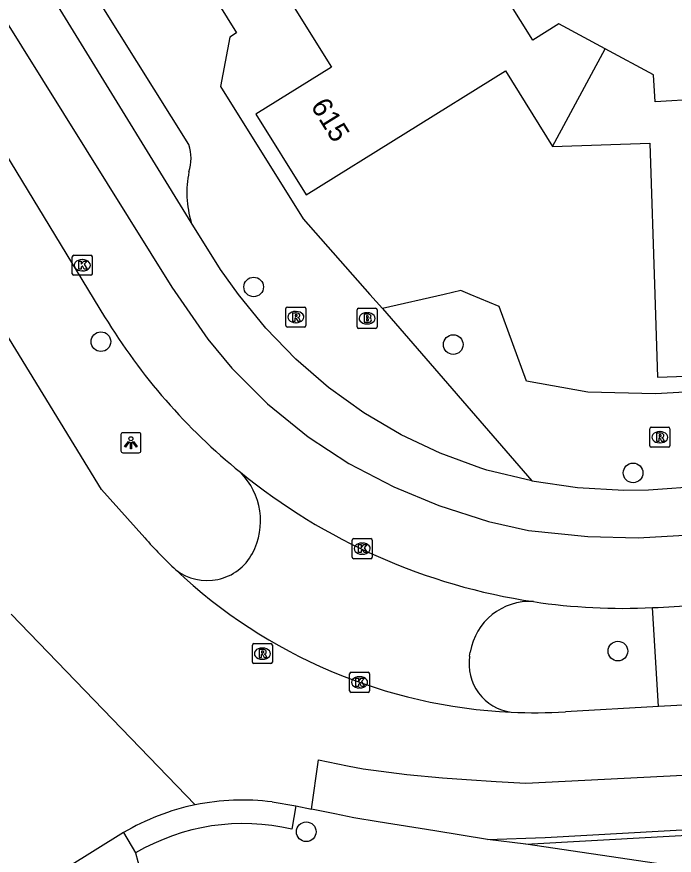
# Model space of a CAD drawing. Extents: x 158461 to 159795, y 387220 to 388672.
# Drawn here: x 158950.89 to 158983.68, y 387722.02 to 387763.85 of the extents above; entities that cross this region are included whole.
import ezdxf

# ---------------------------------------------------------------- set-up
doc = ezdxf.new("R2010")
doc.units = 0
for name, color, linetype in [('IMGEO_Boom', 7, 'Continuous'), ('IMGEO_Brandkraan', 7, 'Continuous'), ('IMGEO_Kolk', 7, 'Continuous'), ('IMGEO_Lichtpunt', 7, 'Continuous'), ('IMGEO_Pand', 7, 'Continuous'), ('IMGEO_Pand_nummerreeks', 7, 'Continuous'), ('IMGEO_Rijbaan_lokaal_gesloten', 7, 'Continuous'), ('IMGEO_Rijbaan_lokaal_open', 7, 'Continuous'), ('IMGEO_Rioolput', 7, 'Continuous'), ('IMGEO_Voetpad_open', 7, 'Continuous')]:
    doc.layers.add(name, color=color, linetype=linetype)

msp = doc.modelspace()

# ---------------------------------------------------------------- linework, layer by layer
at = {"layer": 'IMGEO_Boom'}
for centre in [(158962.704, 387750.372), (158955.083, 387747.643), (158972.658, 387747.498), (158981.631, 387741.095), (158980.875, 387732.205), (158965.326, 387723.193)]:
    msp.add_circle(centre, 0.489, dxfattribs=at)
at = {"layer": 'IMGEO_Brandkraan'}
for p, q in [((158967.862, 387748.381), (158967.862, 387749.233)), ((158967.937, 387749.307), (158968.789, 387749.307)), ((158968.863, 387749.233), (158968.863, 387748.381)), ((158968.35, 387749.087), (158968.375, 387749.087)), ((158968.789, 387748.307), (158967.937, 387748.307)), ((158968.373, 387748.527), (158968.348, 387748.527))]:
    msp.add_line(p, q, dxfattribs=at)
for points in [[(158967.862, 387748.381), (158967.862, 387749.233)], [(158967.937, 387749.307), (158968.789, 387749.307)], [(158968.863, 387749.233), (158968.863, 387748.381)], [(158968.21, 387749.007), (158968.21, 387748.607), (158968.423, 387748.607)], [(158968.441, 387749.007), (158968.21, 387749.007)], [(158968.389, 387748.926), (158968.335, 387748.926), (158968.335, 387748.85)], [(158968.335, 387748.85), (158968.388, 387748.85)], [(158968.397, 387748.774), (158968.335, 387748.774), (158968.335, 387748.693)], [(158968.335, 387748.693), (158968.397, 387748.693)], [(158968.789, 387748.307), (158967.937, 387748.307)]]:
    msp.add_lwpolyline(points, dxfattribs=at)
for centre, radius, start, end in [((158967.939, 387749.231), 0.0765, 91.552, 178.448), ((158967.939, 387749.231), 0.0765, 91.552, 178.448), ((158968.787, 387749.231), 0.0765, 1.552, 88.448), ((158968.787, 387749.231), 0.0765, 1.552, 88.448), ((158968.39, 387748.888), 0.0379, 267.8285, 90.9355), ((158968.398, 387748.733), 0.0404, 269.8759, 90.5077), ((158968.445, 387748.862), 0.145, 59.4692, 91.5367), ((158968.47, 387748.909), 0.0922, 285.5137, 58.1501), ((158968.475, 387748.717), 0.105, 301.3115, 78.989), ((158967.939, 387748.383), 0.0765, 181.552, 268.448), ((158967.939, 387748.383), 0.0765, 181.552, 268.448), ((158968.429, 387748.858), 0.251, 268.6676, 293.5347), ((158968.787, 387748.383), 0.0765, 271.552, 358.448), ((158968.787, 387748.383), 0.0765, 271.552, 358.448)]:
    msp.add_arc(centre, radius, start, end, dxfattribs=at)
for centre, major_axis, ratio, start_param, end_param in [((158968.349, 387748.807), (-0.387, 0.002), 0.722429, 4.712389, 7.853982), ((158968.374, 387748.807), (-0.39, 0.002), 0.717154, 1.570796, 4.712389)]:
    msp.add_ellipse(centre, major_axis=major_axis, ratio=ratio, start_param=start_param, end_param=end_param, dxfattribs=at)
at = {"layer": 'IMGEO_Kolk'}
for p, q in [((158953.654, 387751.028), (158953.654, 387751.88)), ((158953.729, 387751.954), (158954.581, 387751.954)), ((158954.142, 387751.734), (158954.167, 387751.734)), ((158954.655, 387751.88), (158954.655, 387751.028)), ((158954.581, 387750.954), (158953.729, 387750.954)), ((158954.165, 387751.174), (158954.14, 387751.174)), ((158967.693, 387737.817), (158968.545, 387737.817)), ((158967.618, 387736.891), (158967.618, 387737.743)), ((158968.106, 387737.597), (158968.131, 387737.597)), ((158968.619, 387737.743), (158968.619, 387736.891)), ((158968.129, 387737.037), (158968.104, 387737.037)), ((158968.545, 387736.817), (158967.693, 387736.817)), ((158967.562, 387731.148), (158968.414, 387731.148)), ((158967.487, 387730.222), (158967.487, 387731.074)), ((158967.975, 387730.928), (158968, 387730.928)), ((158968.488, 387731.074), (158968.488, 387730.222)), ((158967.998, 387730.368), (158967.973, 387730.368)), ((158968.414, 387730.148), (158967.562, 387730.148))]:
    msp.add_line(p, q, dxfattribs=at)
for points in [[(158953.654, 387751.028), (158953.654, 387751.88)], [(158953.729, 387751.954), (158954.581, 387751.954)], [(158953.975, 387751.654), (158954.098, 387751.654), (158954.098, 387751.503), (158954.228, 387751.654), (158954.392, 387751.654), (158954.246, 387751.503), (158954.399, 387751.254), (158954.247, 387751.254), (158954.162, 387751.418), (158954.098, 387751.351), (158954.098, 387751.254), (158953.975, 387751.254), (158953.975, 387751.654)], [(158954.655, 387751.88), (158954.655, 387751.028)], [(158954.581, 387750.954), (158953.729, 387750.954)], [(158967.693, 387737.817), (158968.545, 387737.817)], [(158967.618, 387736.891), (158967.618, 387737.743)], [(158967.939, 387737.517), (158968.062, 387737.517), (158968.062, 387737.366), (158968.192, 387737.517), (158968.356, 387737.517), (158968.21, 387737.366), (158968.363, 387737.117), (158968.211, 387737.117), (158968.126, 387737.281), (158968.062, 387737.214), (158968.062, 387737.117), (158967.939, 387737.117), (158967.939, 387737.517)], [(158968.619, 387737.743), (158968.619, 387736.891)], [(158968.545, 387736.817), (158967.693, 387736.817)], [(158967.562, 387731.148), (158968.414, 387731.148)], [(158967.487, 387730.222), (158967.487, 387731.074)], [(158967.808, 387730.848), (158967.931, 387730.848), (158967.931, 387730.697), (158968.061, 387730.848), (158968.225, 387730.848), (158968.079, 387730.697), (158968.232, 387730.448), (158968.08, 387730.448), (158967.995, 387730.612), (158967.931, 387730.545), (158967.931, 387730.448), (158967.808, 387730.448), (158967.808, 387730.848)], [(158968.488, 387731.074), (158968.488, 387730.222)], [(158968.414, 387730.148), (158967.562, 387730.148)]]:
    msp.add_lwpolyline(points, dxfattribs=at)
for centre, start, end in [((158953.731, 387751.878), 91.552, 178.448), ((158953.731, 387751.878), 91.552, 178.448), ((158954.579, 387751.878), 1.552, 88.448), ((158954.579, 387751.878), 1.552, 88.448), ((158953.731, 387751.03), 181.552, 268.448), ((158953.731, 387751.03), 181.552, 268.448), ((158954.579, 387751.03), 271.552, 358.448), ((158954.579, 387751.03), 271.552, 358.448), ((158967.695, 387737.741), 91.552, 178.448), ((158967.695, 387737.741), 91.552, 178.448), ((158968.543, 387737.741), 1.552, 88.448), ((158968.543, 387737.741), 1.552, 88.448), ((158967.695, 387736.893), 181.552, 268.448), ((158967.695, 387736.893), 181.552, 268.448), ((158968.543, 387736.893), 271.552, 358.448), ((158968.543, 387736.893), 271.552, 358.448), ((158967.564, 387731.072), 91.552, 178.448), ((158967.564, 387731.072), 91.552, 178.448), ((158968.412, 387731.072), 1.552, 88.448), ((158968.412, 387731.072), 1.552, 88.448), ((158967.564, 387730.224), 181.552, 268.448), ((158967.564, 387730.224), 181.552, 268.448), ((158968.412, 387730.224), 271.552, 358.448), ((158968.412, 387730.224), 271.552, 358.448)]:
    msp.add_arc(centre, 0.0765, start, end, dxfattribs=at)
for centre, major_axis, ratio, start_param, end_param in [((158954.141, 387751.454), (-0.387, 0.002), 0.722429, 4.712389, 7.853982), ((158954.166, 387751.454), (-0.39, 0.002), 0.717154, 1.570796, 4.712389), ((158968.105, 387737.317), (-0.387, 0.002), 0.722429, 4.712389, 7.853982), ((158968.13, 387737.317), (-0.39, 0.002), 0.717154, 1.570796, 4.712389), ((158967.974, 387730.648), (-0.387, 0.002), 0.722429, 4.712389, 7.853982), ((158967.999, 387730.648), (-0.39, 0.002), 0.717154, 1.570796, 4.712389)]:
    msp.add_ellipse(centre, major_axis=major_axis, ratio=ratio, start_param=start_param, end_param=end_param, dxfattribs=at)
at = {"layer": 'IMGEO_Lichtpunt'}
for p, q in [((158956.081, 387743.004), (158956.081, 387742.197)), ((158956.081, 387743.004), (158956.081, 387742.197)), ((158956.983, 387743.099), (158956.175, 387743.099)), ((158956.983, 387743.099), (158956.175, 387743.099)), ((158957.077, 387742.197), (158957.077, 387743.004)), ((158957.077, 387742.197), (158957.077, 387743.004)), ((158956.175, 387742.103), (158956.983, 387742.103)), ((158956.175, 387742.103), (158956.983, 387742.103))]:
    msp.add_line(p, q, dxfattribs=at)
for points in [[(158956.455, 387742.668), (158956.494, 387742.64), (158956.306, 387742.378), (158956.268, 387742.405), (158956.455, 387742.668)], [(158956.557, 387742.62), (158956.604, 387742.62), (158956.604, 387742.298), (158956.557, 387742.298), (158956.557, 387742.62)], [(158956.667, 387742.64), (158956.705, 387742.667), (158956.892, 387742.405), (158956.853, 387742.377), (158956.667, 387742.64)]]:
    msp.add_lwpolyline(points, dxfattribs=at)
msp.add_circle((158956.58, 387742.802), 0.0994, dxfattribs=at)
for centre, start, end in [((158956.175, 387743.004), 90, 180), ((158956.175, 387743.004), 90, 180), ((158956.983, 387743.004), 0, 90), ((158956.983, 387743.004), 0, 90), ((158956.175, 387742.197), 180, 270), ((158956.175, 387742.197), 180, 270), ((158956.983, 387742.197), 270, 0), ((158956.983, 387742.197), 270, 360)]:
    msp.add_arc(centre, 0.0946, start, end, dxfattribs=at)
at = {"layer": 'IMGEO_Pand'}
for points in [[(158980.245, 387762.254), (158977.935, 387763.495), (158976.624, 387762.679), (158974.165, 387766.629)], [(158964.468, 387764.726), (158966.581, 387761.331), (158962.812, 387758.985), (158965.317, 387754.961), (158975.259, 387761.149), (158977.604, 387757.38)], [(158977.604, 387757.38), (158980.245, 387762.254)], [(158987.15, 387759.865), (158982.73, 387759.611), (158982.652, 387760.96), (158980.245, 387762.254)], [(158977.604, 387757.38), (158982.462, 387757.541), (158982.712, 387750), (158982.849, 387745.874), (158987.604, 387746.031), (158987.473, 387750), (158987.453, 387750.601), (158991.981, 387750.857)]]:
    msp.add_lwpolyline(points, dxfattribs=at)
at = {"layer": 'IMGEO_Rijbaan_lokaal_gesloten'}
for points in [[(158887.922, 387863.502), (158910.852, 387826.792), (158942.469, 387776.24), (158958.617, 387750.353), (158960.418, 387747.762), (158961.612, 387746.321), (158963.393, 387744.535), (158965.421, 387742.895), (158967.458, 387741.572), (158969.689, 387740.407), (158971.94, 387739.465), (158974.416, 387738.664), (158976.417, 387738.226), (158979.369, 387737.931), (158981.889, 387737.858), (159007.45, 387739.32), (159019.867, 387740.171), (159032.856, 387742.163)], [(158959.591, 387753.588), (158948.358, 387771.822), (158935.188, 387792.904), (158922.531, 387813.295), (158913.231, 387828.204), (158908.724, 387835.428), (158907.553, 387837.293)], [(158950.329, 387757.013), (158955.27, 387748.888)], [(158957.267, 387737.857), (158955.113, 387740.269), (158950.163, 387748.361), (158949.133, 387750), (158946.243, 387754.475)], [(158976.58, 387740.699), (158974.334, 387741.233), (158974.035, 387741.326), (158972.009, 387742.075), (158970.058, 387743.002), (158968.197, 387744.099), (158966.443, 387745.358), (158964.807, 387746.769), (158963.304, 387748.321), (158961.946, 387750), (158961.046, 387751.246), (158959.591, 387753.588)], [(158976.58, 387740.699), (158978.865, 387740.368), (158981.171, 387740.242), (158982.397, 387740.259), (158985.18, 387740.45)], [(158982.6, 387734.374), (158982.875, 387734.389), (158984.743, 387734.496)], [(158950.607, 387734.056), (158959.793, 387724.538)], [(158982.896, 387729.442), (158978.256, 387729.175)], [(158985.039, 387729.565), (158982.896, 387729.442)], [(158965.591, 387724.322), (158965.932, 387726.779), (158967.392, 387726.477), (158968.163, 387726.336), (158970.34, 387726.046), (158972.125, 387725.889), (158973.313, 387725.803), (158974.8, 387725.707), (158976.288, 387725.617), (158996.546, 387726.65), (159030.787, 387728.616), (159033.217, 387728.616), (159034.104, 387728.548), (159034.99, 387728.468), (159035.499, 387728.412), (159036.753, 387728.237), (159037.631, 387728.097), (159038.26, 387727.989), (159043.465, 387727.098), (159045.801, 387726.729), (159046.831, 387726.625), (159048.016, 387726.551)], [(158974.362, 387722.8), (158977.244, 387722.906), (159022.96, 387725.469), (159024.209, 387725.614)], [(159022.447, 387725.145), (159009.709, 387721.727), (158989.772, 387720.574), (158976.287, 387722.576)], [(158976.287, 387722.576), (159022.447, 387725.145)], [(158963.626, 387724.68), (158964.813, 387724.483)], [(158964.813, 387724.483), (158965.591, 387724.322)], [(158974.362, 387722.8), (158971.743, 387723.241), (158968.918, 387723.697), (158967.694, 387723.895), (158966.752, 387724.082), (158965.591, 387724.322)], [(158956.215, 387723.154), (158935.881, 387710.493)]]:
    msp.add_lwpolyline(points, dxfattribs=at)
for centre, radius, start, end in [((158981.128, 387764.611), 30.263, 211.3024, 230.8935), ((158981.144, 387764.621), 30.281, 230.8811, 261.4837), ((158976.338, 387754.858), 25.549, 221.7155, 226.7238), ((158976.758, 387755.265), 26.133, 226.6651, 267.3411), ((158981.152, 387764.653), 30.314, 261.4789, 272.7385), ((158976.758, 387755.01), 25.878, 267.3157, 273.3186), ((158962.126, 387713.189), 11.586, 101.6171, 120.6767), ((158962.134, 387713.137), 11.639, 82.6373, 101.606)]:
    msp.add_arc(centre, radius, start, end, dxfattribs=at)
at = {"layer": 'IMGEO_Rijbaan_lokaal_open'}
for points in [[(158973.477, 387731.947), (158973.511, 387732.16)], [(158976.287, 387722.576), (158974.362, 387722.8)]]:
    msp.add_lwpolyline(points, dxfattribs=at)
for centre, radius, start, end in [((158959.613, 387738.697), 3.434, 331.7888, 45.0488), ((158960.385, 387738.285), 2.559, 232.4274, 331.7477), ((158976.474, 387731.678), 3.002, 86.4399, 170.7643), ((158975.868, 387731.56), 2.422, 170.8118, 262.3667)]:
    msp.add_arc(centre, radius, start, end, dxfattribs=at)
at = {"layer": 'IMGEO_Rioolput'}
for p, q in [((158964.309, 387748.443), (158964.309, 387749.295)), ((158964.384, 387749.369), (158965.236, 387749.369)), ((158964.797, 387749.149), (158964.822, 387749.149)), ((158965.31, 387749.295), (158965.31, 387748.443)), ((158965.236, 387748.369), (158964.384, 387748.369)), ((158964.82, 387748.589), (158964.795, 387748.589)), ((158982.465, 387742.45), (158982.465, 387743.302)), ((158982.54, 387743.376), (158983.392, 387743.376)), ((158983.466, 387743.302), (158983.466, 387742.45)), ((158982.953, 387743.156), (158982.978, 387743.156)), ((158982.976, 387742.596), (158982.951, 387742.596)), ((158983.392, 387742.376), (158982.54, 387742.376)), ((158962.638, 387731.654), (158962.638, 387732.506)), ((158962.713, 387732.58), (158963.565, 387732.58)), ((158963.639, 387732.506), (158963.639, 387731.654)), ((158963.126, 387732.36), (158963.151, 387732.36)), ((158963.565, 387731.58), (158962.713, 387731.58)), ((158963.149, 387731.8), (158963.124, 387731.8))]:
    msp.add_line(p, q, dxfattribs=at)
for points in [[(158964.309, 387748.443), (158964.309, 387749.295)], [(158964.384, 387749.369), (158965.236, 387749.369)], [(158965.31, 387749.295), (158965.31, 387748.443)], [(158964.898, 387749.067), (158964.646, 387749.069), (158964.646, 387748.669)], [(158964.646, 387748.669), (158964.77, 387748.669), (158964.77, 387748.831), (158964.781, 387748.831)], [(158964.824, 387748.988), (158964.77, 387748.988), (158964.77, 387748.907)], [(158964.77, 387748.907), (158964.822, 387748.907)], [(158964.828, 387748.802), (158964.899, 387748.669), (158965.039, 387748.669), (158964.974, 387748.795)], [(158965.236, 387748.369), (158964.384, 387748.369)], [(158982.465, 387742.45), (158982.465, 387743.302)], [(158982.54, 387743.376), (158983.392, 387743.376)], [(158983.466, 387743.302), (158983.466, 387742.45)], [(158983.054, 387743.074), (158982.802, 387743.076), (158982.802, 387742.676)], [(158982.802, 387742.676), (158982.926, 387742.676), (158982.926, 387742.838), (158982.937, 387742.838)], [(158982.98, 387742.995), (158982.926, 387742.995), (158982.926, 387742.914)], [(158982.926, 387742.914), (158982.978, 387742.914)], [(158982.984, 387742.809), (158983.055, 387742.676), (158983.195, 387742.676), (158983.13, 387742.802)], [(158983.392, 387742.376), (158982.54, 387742.376)], [(158962.638, 387731.654), (158962.638, 387732.506)], [(158962.713, 387732.58), (158963.565, 387732.58)], [(158963.639, 387732.506), (158963.639, 387731.654)], [(158963.227, 387732.278), (158962.975, 387732.28), (158962.975, 387731.88)], [(158962.975, 387731.88), (158963.099, 387731.88), (158963.099, 387732.042), (158963.11, 387732.042)], [(158963.153, 387732.199), (158963.099, 387732.199), (158963.099, 387732.118)], [(158963.099, 387732.118), (158963.151, 387732.118)], [(158963.157, 387732.013), (158963.228, 387731.88), (158963.368, 387731.88), (158963.303, 387732.006)], [(158963.565, 387731.58), (158962.713, 387731.58)]]:
    msp.add_lwpolyline(points, dxfattribs=at)
for centre, radius, start, end in [((158964.386, 387749.293), 0.0765, 91.552, 178.448), ((158964.386, 387749.293), 0.0765, 91.552, 178.448), ((158965.234, 387749.293), 0.0765, 1.552, 88.448), ((158965.234, 387749.293), 0.0765, 1.552, 88.448), ((158964.78, 387748.778), 0.0533, 26.0293, 88.6989), ((158964.806, 387749.096), 0.19, 274.7715, 282.9687), ((158964.83, 387748.892), 0.0964, 77.0061, 93.1865), ((158964.844, 387748.949), 0.0378, 276.6634, 79.6772), ((158964.897, 387748.957), 0.109, 350.3612, 89.416), ((158964.895, 387748.957), 0.112, 277.5842, 350.9817), ((158964.879, 387748.742), 0.108, 29.5134, 73.7905), ((158964.386, 387748.445), 0.0765, 181.552, 268.448), ((158964.386, 387748.445), 0.0765, 181.552, 268.448), ((158965.234, 387748.445), 0.0765, 271.552, 358.448), ((158965.234, 387748.445), 0.0765, 271.552, 358.448), ((158982.542, 387743.3), 0.0765, 91.552, 178.448), ((158982.542, 387743.3), 0.0765, 91.552, 178.448), ((158983.39, 387743.3), 0.0765, 1.552, 88.448), ((158983.39, 387743.3), 0.0765, 1.552, 88.448), ((158982.936, 387742.785), 0.0533, 26.0293, 88.6989), ((158982.962, 387743.103), 0.19, 274.7715, 282.9687), ((158982.986, 387742.899), 0.0964, 77.0061, 93.1865), ((158983, 387742.956), 0.0378, 276.6634, 79.6772), ((158983.053, 387742.964), 0.109, 350.3612, 89.416), ((158983.051, 387742.964), 0.112, 277.5842, 350.9817), ((158983.035, 387742.749), 0.108, 29.5134, 73.7905), ((158982.542, 387742.452), 0.0765, 181.552, 268.448), ((158982.542, 387742.452), 0.0765, 181.552, 268.448), ((158983.39, 387742.452), 0.0765, 271.552, 358.448), ((158983.39, 387742.452), 0.0765, 271.552, 358.448), ((158962.715, 387732.504), 0.0765, 91.552, 178.448), ((158962.715, 387732.504), 0.0765, 91.552, 178.448), ((158963.563, 387732.504), 0.0765, 1.552, 88.448), ((158963.563, 387732.504), 0.0765, 1.552, 88.448), ((158963.109, 387731.989), 0.0533, 26.0293, 88.6989), ((158963.135, 387732.307), 0.19, 274.7715, 282.9687), ((158963.159, 387732.103), 0.0964, 77.0061, 93.1865), ((158963.173, 387732.16), 0.0378, 276.6634, 79.6772), ((158963.226, 387732.168), 0.109, 350.3612, 89.416), ((158963.224, 387732.168), 0.112, 277.5842, 350.9817), ((158963.208, 387731.953), 0.108, 29.5134, 73.7905), ((158962.715, 387731.656), 0.0765, 181.552, 268.448), ((158962.715, 387731.656), 0.0765, 181.552, 268.448), ((158963.563, 387731.656), 0.0765, 271.552, 358.448), ((158963.563, 387731.656), 0.0765, 271.552, 358.448)]:
    msp.add_arc(centre, radius, start, end, dxfattribs=at)
for centre, major_axis, ratio, start_param, end_param in [((158964.796, 387748.869), (-0.387, 0.002), 0.722429, 4.712389, 7.853982), ((158964.821, 387748.869), (-0.39, 0.002), 0.717154, 1.570796, 4.712389), ((158982.952, 387742.876), (-0.387, 0.002), 0.722429, 4.712389, 7.853982), ((158982.977, 387742.876), (-0.39, 0.002), 0.717154, 1.570796, 4.712389), ((158963.125, 387732.08), (-0.387, 0.002), 0.722429, 4.712389, 7.853982), ((158963.15, 387732.08), (-0.39, 0.002), 0.717154, 1.570796, 4.712389)]:
    msp.add_ellipse(centre, major_axis=major_axis, ratio=ratio, start_param=start_param, end_param=end_param, dxfattribs=at)
at = {"layer": 'IMGEO_Voetpad_open'}
for points in [[(158959.476, 387757.471), (158914.647, 387828.995), (158910.604, 387835.446)], [(158945.564, 387785.349), (158953.827, 387771.988), (158956.246, 387771.106), (158956.636, 387771.426), (158961.841, 387763.046), (158961.521, 387762.826), (158961.041, 387760.377), (158965.166, 387753.767), (158968.506, 387750), (158969.131, 387749.295)], [(159019.359, 387747.168), (159003.595, 387746.159), (159001.516, 387747.8), (159001.476, 387748.19), (159000, 387748.121), (158991.639, 387747.729), (158991.689, 387747.309), (158989.75, 387745.431), (158982.752, 387745.036), (158979.374, 387745.118), (158976.31, 387745.668), (158974.954, 387749.404), (158973.504, 387750), (158973.039, 387750.191), (158972.206, 387750), (158969.131, 387749.295)], [(158969.131, 387749.295), (158976.58, 387740.699)], [(158982.896, 387729.442), (158982.6, 387734.374)], [(158964.813, 387724.483), (158964.613, 387723.326)], [(158956.215, 387723.154), (158956.816, 387722.141)], [(158956.816, 387722.141), (158957.387, 387719.979)]]:
    msp.add_lwpolyline(points, dxfattribs=at)
for centre, radius, start, end in [((158957.297, 387756.793), 2.282, 342.6366, 17.2791), ((158964.527, 387755.08), 5.156, 168.4493, 196.8135), ((158962.199, 387712.968), 10.635, 76.8784, 120.4051)]:
    msp.add_arc(centre, radius, start, end, dxfattribs=at)

# ---------------------------------------------------------------- texts
at = {"layer": 'IMGEO_Pand_nummerreeks'}
msp.add_text('615', height=1, rotation=301.9029, dxfattribs=at).set_placement((158965.523, 387759.398))

doc.saveas('drawing.dxf')
